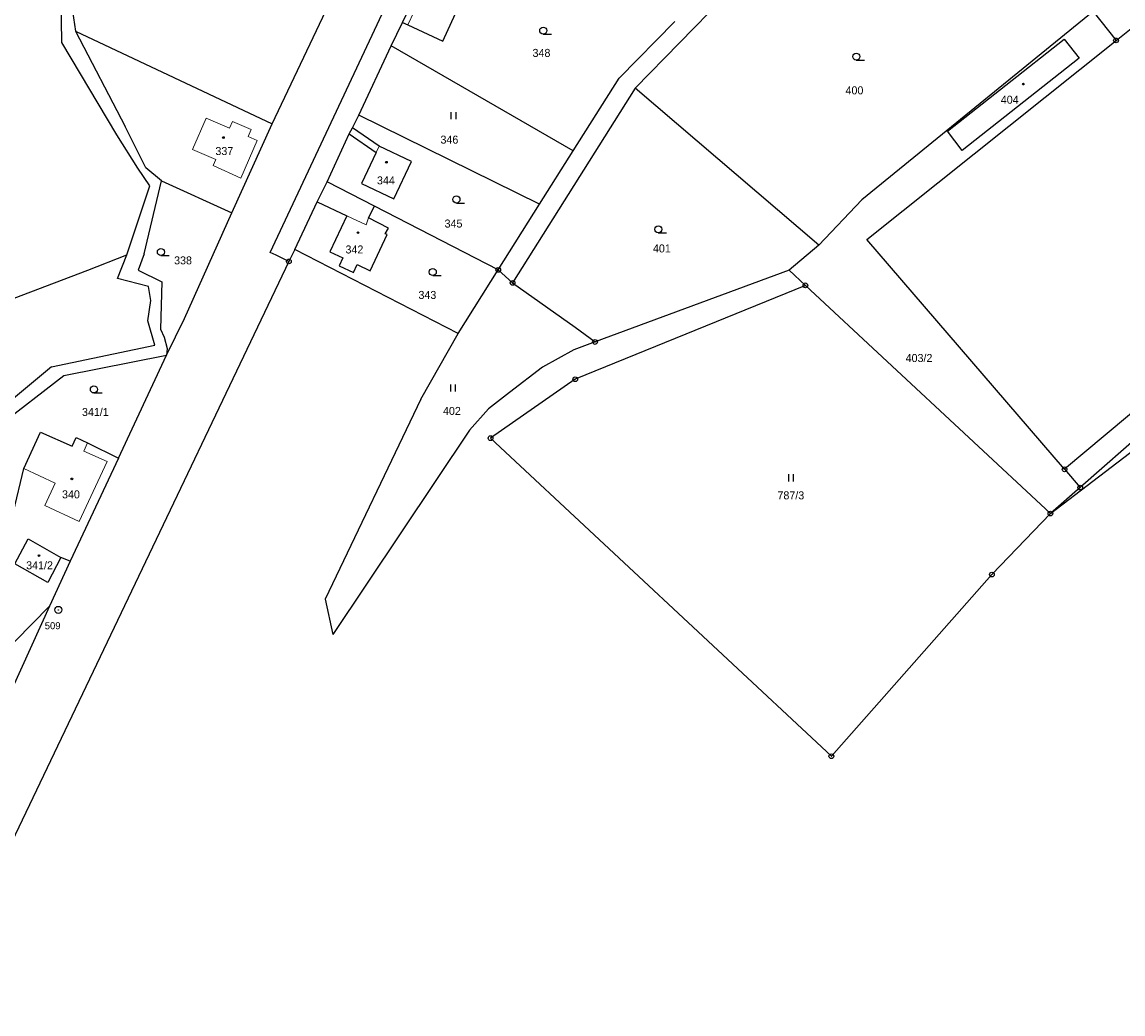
# Model space of a CAD drawing. Extents: x -727701 to -724405, y -960481 to -957284.
# Drawn here: x -727182.9 to -726949, y -958649.2 to -958438.5 of the extents above; entities that cross this region are included whole.
import ezdxf
from ezdxf.enums import TextEntityAlignment as Align

# ---------------------------------------------------------------- set-up
doc = ezdxf.new("R2010")
doc.units = 0
doc.header["$LTSCALE"] = 0.68
for name, color, linetype, lineweight in [('1', 7, 'Continuous', 25), ('3', 7, 'Continuous', 25), ('4', 7, 'Continuous', 13), ('5', 7, 'Continuous', 25), ('8', 7, 'Continuous', 25)]:
    doc.layers.add(name, color=color, linetype=linetype, lineweight=lineweight)
doc.layers.add('2', color=7, linetype='Continuous')

msp = doc.modelspace()

# ---------------------------------------------------------------- linework, layer by layer
at = {"layer": '1'}
for p, q in [((-727130.21, -958487.42), (-727073.19, -958365.95)), ((-727129.81, -958460.09), (-727105.33, -958408.62)), ((-727102.09, -958438.57), (-727088.68, -958410.97)), ((-727052.66, -958452.54), (-727012.58, -958411.52)), ((-726950.5, -958442.38), (-726927.59, -958424.09)), ((-727174.46, -958442.83), (-727174.6, -958431.04)), ((-727172.67, -958432.73), (-727171.59, -958440.46)), ((-727093.55, -958442.53), (-727088.5, -958431.65)), ((-726955.38, -958436.25), (-727004.47, -958476.25)), ((-726955.38, -958436.25), (-726950.5, -958442.38)), ((-727104.51, -958443.56), (-727102.09, -958438.57)), ((-727102.09, -958438.57), (-727100.93, -958439.11)), ((-727100.93, -958439.11), (-727093.55, -958442.53)), ((-727056.09, -958450.38), (-727044.25, -958438.4)), ((-727171.59, -958440.46), (-727161, -958460.67)), ((-727171.59, -958440.46), (-727129.81, -958460.09)), ((-727003.46, -958484.67), (-726950.5, -958442.38)), ((-726961.51, -958442.14), (-726958.33, -958446.17)), ((-727162.8, -958462.42), (-727174.46, -958442.83)), ((-727111.34, -958458.3), (-727104.51, -958443.56)), ((-727065.83, -958465.85), (-727104.51, -958443.56)), ((-726958.33, -958446.17), (-726983.17, -958465.75)), ((-727065.83, -958465.85), (-727056.09, -958450.38)), ((-727052.66, -958452.54), (-727078.69, -958493.89)), ((-727013.65, -958485.9), (-727052.66, -958452.54)), ((-727112.69, -958460.96), (-727111.34, -958458.3)), ((-727072.97, -958477.2), (-727111.34, -958458.3)), ((-727156.59, -958469.48), (-727161, -958460.67)), ((-727138.32, -958479.05), (-727129.81, -958460.09)), ((-727113.41, -958462.25), (-727112.69, -958460.96)), ((-727107.04, -958464.86), (-727112.69, -958460.96)), ((-727158.31, -958469.51), (-727162.8, -958462.42)), ((-727118.1, -958472.46), (-727113.41, -958462.25)), ((-727113.41, -958462.25), (-727107.69, -958466.23)), ((-727100.16, -958468.14), (-727107.04, -958464.86)), ((-727072.97, -958477.2), (-727065.83, -958465.85)), ((-726875.45, -958464.8), (-726958.11, -958537.36)), ((-727107.69, -958466.23), (-727110.82, -958472.78)), ((-727103.94, -958476.06), (-727100.16, -958468.14)), ((-727155.74, -958473.31), (-727158.31, -958469.51)), ((-727153.32, -958472.2), (-727156.59, -958469.48)), ((-726885.45, -958469.72), (-726961.43, -958533.5)), ((-727156.96, -958487.76), (-727153.32, -958472.2)), ((-727153.32, -958472.2), (-727138.32, -958479.05)), ((-727120.19, -958476.71), (-727118.1, -958472.46)), ((-727108.05, -958477.63), (-727118.1, -958472.46)), ((-727110.82, -958472.78), (-727103.94, -958476.06)), ((-727160.62, -958487.96), (-727155.74, -958473.31)), ((-727124.99, -958486.78), (-727120.19, -958476.71)), ((-727120.19, -958476.71), (-727113.92, -958479.63)), ((-727081.76, -958491.15), (-727072.97, -958477.2)), ((-727004.47, -958476.25), (-727013.65, -958485.9)), ((-727148.37, -958501.43), (-727138.32, -958479.05)), ((-727113.92, -958479.63), (-727117.53, -958487.28)), ((-727109.31, -958480.08), (-727108.05, -958477.63)), ((-727081.76, -958491.15), (-727108.05, -958477.63)), ((-727105.07, -958482.28), (-727109.31, -958480.08)), ((-727108.98, -958491.31), (-727105.38, -958483.65)), ((-727105.74, -958483.49), (-727105.07, -958482.28)), ((-727105.38, -958483.65), (-727105.74, -958483.49)), ((-727124.99, -958486.78), (-727126.21, -958489.34)), ((-727090.27, -958504.68), (-727124.99, -958486.78)), ((-727013.65, -958485.9), (-727019.97, -958491.18)), ((-726961.43, -958533.5), (-727003.46, -958484.67)), ((-727168.95, -958491.2), (-727160.62, -958487.96)), ((-727162.64, -958492.99), (-727160.62, -958487.96)), ((-727156.96, -958487.76), (-727158.23, -958491.21)), ((-727128.96, -958488.01), (-727130.21, -958487.42)), ((-727126.21, -958489.34), (-727128.96, -958488.01)), ((-727117.53, -958487.28), (-727114.78, -958488.57)), ((-727114.78, -958488.57), (-727115.57, -958490.25)), ((-727270.12, -958529.43), (-727168.95, -958491.2)), ((-727126.21, -958489.34), (-727164.84, -958570.18)), ((-727158.23, -958491.21), (-727153.25, -958493.67)), ((-727115.57, -958490.25), (-727112.51, -958491.69)), ((-727112.51, -958491.69), (-727111.73, -958490.01)), ((-727111.73, -958490.01), (-727108.98, -958491.31)), ((-727090.27, -958504.68), (-727081.76, -958491.15)), ((-727081.76, -958491.15), (-727078.69, -958493.89)), ((-727019.97, -958491.18), (-727061.19, -958506.45)), ((-727019.97, -958491.18), (-727016.49, -958494.42)), ((-727156.02, -958494.66), (-727162.64, -958492.99)), ((-727153.25, -958493.67), (-727153.52, -958503.75)), ((-727155.55, -958497.65), (-727156.02, -958494.66)), ((-727016.49, -958494.42), (-727065.4, -958514.37)), ((-727016.49, -958494.42), (-726964.44, -958542.91)), ((-727156.2, -958501.99), (-727155.55, -958497.65)), ((-727154.73, -958507.16), (-727156.2, -958501.99)), ((-727152.2, -958509.25), (-727148.37, -958501.43)), ((-727153.52, -958503.75), (-727152.7, -958505.4)), ((-727152.7, -958505.4), (-727152.1, -958507.8)), ((-727098.22, -958518.59), (-727090.27, -958504.68)), ((-727176.67, -958511.72), (-727154.73, -958507.16)), ((-727152.1, -958507.8), (-727152.2, -958509.25)), ((-727061.19, -958506.45), (-727065.71, -958508.12)), ((-727174.02, -958513.59), (-727152.2, -958509.25)), ((-727162.43, -958531.13), (-727152.2, -958509.25)), ((-727065.71, -958508.12), (-727072.33, -958511.8)), ((-727176.67, -958511.72), (-727190.2, -958523)), ((-727072.33, -958511.8), (-727079.37, -958517.15)), ((-727188.86, -958524.99), (-727174.02, -958513.59)), ((-727065.4, -958514.37), (-727083.39, -958526.88)), ((-727079.37, -958517.15), (-727083.82, -958520.62)), ((-726964.44, -958542.91), (-726929.23, -958515.98)), ((-727098.22, -958518.59), (-727118.52, -958561.11)), ((-727083.82, -958520.62), (-727087.88, -958525.21)), ((-727182.54, -958533.32), (-727179, -958525.57)), ((-727179, -958525.57), (-727172.25, -958528.57)), ((-727087.88, -958525.21), (-727116.92, -958568.61)), ((-727172.25, -958528.57), (-727171.45, -958526.77)), ((-727171.45, -958526.77), (-727168.99, -958527.86)), ((-727168.99, -958527.86), (-727162.43, -958531.13)), ((-727083.39, -958526.88), (-727010.98, -958594.43)), ((-727162.43, -958531.13), (-727172.66, -958553.03)), ((-727186.91, -958551.7), (-727182.54, -958533.32)), ((-726961.43, -958533.5), (-726958.11, -958537.36)), ((-726958.11, -958537.36), (-726964.44, -958542.91)), ((-726976.88, -958555.85), (-726964.44, -958542.91)), ((-727184.43, -958553.59), (-727181.63, -958548.27)), ((-727181.63, -958548.27), (-727174.67, -958552.2)), ((-727174.67, -958552.2), (-727177.45, -958557.53)), ((-727172.66, -958553.03), (-727174.67, -958552.2)), ((-727177.45, -958557.53), (-727184.43, -958553.59)), ((-727172.66, -958553.03), (-727177.11, -958562.54)), ((-727010.98, -958594.43), (-726976.88, -958555.85)), ((-727118.52, -958561.11), (-727116.92, -958568.61)), ((-727177.11, -958562.54), (-727188.06, -958573.67)), ((-727177.11, -958562.54), (-727184.92, -958579.92)), ((-727164.84, -958570.18), (-727225.49, -958697.14))]:
    msp.add_line(p, q, dxfattribs=at)
for points in [[(-726983.17, -958465.75), (-726986.32, -958461.7), (-726961.51, -958442.14)], [(-727078.69, -958493.89), (-727065.37, -958503.3), (-727061.19, -958506.45)]]:
    msp.add_lwpolyline(points, dxfattribs=at)
at = {"layer": '3'}
for p, q in [((-727072.193, -958441.06), (-727070.443, -958441.06)), ((-727005.683, -958446.58), (-727003.933, -958446.58)), ((-727091.721, -958459.11), (-727091.721, -958457.61)), ((-727090.72, -958459.11), (-727090.72, -958457.61)), ((-727090.633, -958476.93), (-727088.883, -958476.93)), ((-727047.743, -958483.27), (-727045.993, -958483.27)), ((-727153.423, -958488.09), (-727151.673, -958488.09)), ((-727095.653, -958492.34), (-727093.903, -958492.34)), ((-727167.653, -958517.28), (-727165.903, -958517.28)), ((-727091.851, -958516.98), (-727091.851, -958515.48)), ((-727090.85, -958516.98), (-727090.85, -958515.48)), ((-727020.031, -958536.06), (-727020.031, -958534.56)), ((-727019.03, -958536.06), (-727019.03, -958534.56))]:
    msp.add_line(p, q, dxfattribs=at)
for centre in [(-727072.1929, -958440.3098), (-727005.6829, -958445.8298), (-727090.6329, -958476.1798), (-727047.7429, -958482.5198), (-727153.4229, -958487.3398), (-727095.6529, -958491.5898), (-727167.6529, -958516.5298)]:
    msp.add_circle(centre, 0.75, dxfattribs=at)
at = {"layer": '4'}
for p, q in [((-727100.93, -958439.11), (-727095.11, -958426.56)), ((-727146.72, -958465.54), (-727143.82, -958458.88)), ((-727143.82, -958458.88), (-727138.84, -958461.05)), ((-727138.84, -958461.05), (-727138.21, -958459.59)), ((-727138.21, -958459.59), (-727134.24, -958461.32)), ((-727134.24, -958461.32), (-727134.88, -958462.78)), ((-727134.88, -958462.78), (-727132.94, -958463.63)), ((-727141.75, -958467.71), (-727146.72, -958465.54)), ((-727132.94, -958463.63), (-727136.43, -958471.62)), ((-727107.69, -958466.23), (-727107.04, -958464.86)), ((-727142.3, -958468.96), (-727141.75, -958467.71)), ((-727136.43, -958471.62), (-727142.3, -958468.96)), ((-727113.92, -958479.63), (-727109.78, -958481.58)), ((-727109.78, -958481.58), (-727109.31, -958480.08)), ((-727169.78, -958529.66), (-727168.99, -958527.86)), ((-727164.81, -958531.87), (-727169.78, -958529.66)), ((-727182.54, -958533.32), (-727175.85, -958536.44)), ((-727170.76, -958544.61), (-727164.81, -958531.87)), ((-727175.85, -958536.44), (-727178.07, -958541.2)), ((-727178.07, -958541.2), (-727170.76, -958544.61))]:
    msp.add_line(p, q, dxfattribs=at)
at = {"layer": '5'}
for centre in [(-726970.1868, -958451.6692), (-727140.1268, -958463.0192), (-727105.4968, -958468.2592), (-727111.5468, -958483.2192), (-727172.3268, -958535.5292), (-727179.3068, -958551.8192)]:
    msp.add_circle(centre, 0.175, dxfattribs=at)
at = {"layer": '8'}
for centre, radius in [((-726950.5, -958442.3799), 0.5), ((-726950.5, -958442.3799), 0.0303), ((-727126.21, -958489.3399), 0.5), ((-727126.21, -958489.3399), 0.0303), ((-727081.76, -958491.1499), 0.5), ((-727081.76, -958491.1499), 0.0303), ((-727078.69, -958493.8899), 0.5), ((-727078.69, -958493.8899), 0.0303), ((-727016.49, -958494.4199), 0.5), ((-727016.49, -958494.4199), 0.0303), ((-727061.19, -958506.4499), 0.5), ((-727061.19, -958506.4499), 0.0303), ((-727065.4, -958514.3699), 0.5), ((-727065.4, -958514.3699), 0.0303), ((-727083.39, -958526.8799), 0.5), ((-727083.39, -958526.8799), 0.0303), ((-726961.43, -958533.4999), 0.5), ((-726961.43, -958533.4999), 0.0303), ((-726958.11, -958537.3599), 0.5), ((-726958.11, -958537.3599), 0.0303), ((-726964.44, -958542.9099), 0.5), ((-726964.44, -958542.9099), 0.0303), ((-726976.88, -958555.8499), 0.5), ((-726976.88, -958555.8499), 0.0303), ((-727175.2, -958563.3598), 0.75), ((-727175.2, -958563.3598), 0.03), ((-727010.98, -958594.4299), 0.5), ((-727010.98, -958594.4299), 0.0303)]:
    msp.add_circle(centre, radius, dxfattribs=at)

# ---------------------------------------------------------------- texts
at = {"layer": '2'}
for s, p in [('348', (-727074.46, -958445.895)), ('400', (-727007.97, -958453.845)), ('404', (-726974.98, -958455.835)), ('346', (-727094.02, -958464.315)), ('337', (-727141.84, -958466.745)), ('344', (-727107.51, -958472.975)), ('345', (-727093.15, -958482.145)), ('342', (-727114.2, -958487.645)), ('401', (-727048.88, -958487.425)), ('338', (-727150.61, -958489.965)), ('343', (-727098.7, -958497.305)), ('340', (-727174.42, -958539.665)), ('787/3', (-727022.43, -958539.875))]:
    msp.add_text(s, height=1.7, dxfattribs=at).set_placement(p)
for s, p in [('403/2', (-726992.35, -958510.705)), ('341/1', (-727167.34, -958522.175)), ('402', (-727091.589, -958521.945)), ('341/2', (-727179.2, -958554.735))]:
    msp.add_text(s, height=1.7, dxfattribs=at).set_placement(p, align=Align.CENTER)
at = {"layer": '8'}
msp.add_text('509', height=1.5, dxfattribs=at).set_placement((-727178.09, -958567.465))

doc.saveas('drawing.dxf')
